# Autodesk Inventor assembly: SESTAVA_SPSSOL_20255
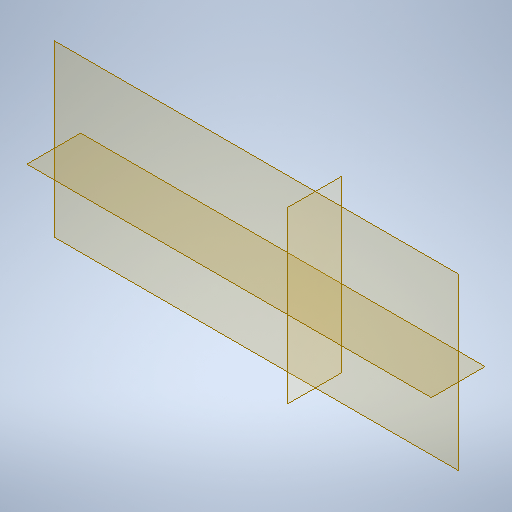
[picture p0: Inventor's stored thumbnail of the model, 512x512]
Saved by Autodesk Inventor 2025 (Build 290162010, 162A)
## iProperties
Part Number: SESTAVA_SPSSOL_20255
Document SubType Name: Assembly
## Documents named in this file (1)
- C:\Users\Public\Documents\Autodesk\Inventor 2025\Templates\SABLONY_SPSSOL_2025\SESTAVA_SPSSOL_20255.iam
